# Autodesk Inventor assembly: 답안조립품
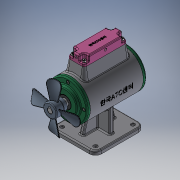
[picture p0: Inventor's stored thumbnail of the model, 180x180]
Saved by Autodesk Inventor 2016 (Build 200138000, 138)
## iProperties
Created: 2021-02
Part Number: 답안조립품
Material: 일반
Document SubType Name: Assembly
Designer: Windows7
Mass: 2275.07 g
Surface Area: 2702.32 cm^2
Volume: 961.297 cm^3
Density: 2.36666 g/cm^3
Author: Windows7
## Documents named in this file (19)
- C:\Users\Windows7\Desktop\610204V1013\답안조립품.iam
- C:\Users\Windows7\Desktop\610204V1013\본체.ipt
- C:\Users\Windows7\Desktop\610204V1013\가변스프링1.ipt
- C:\Users\Windows7\Desktop\610204V1013\가변스프링2.ipt
- C:\Users\Windows7\Desktop\610204V1013\가변스프링3.ipt
- C:\Users\Windows7\Desktop\610204V1013\뒤커버.ipt
- C:\Users\Windows7\Desktop\610204V1013\멈춤나사 M4 x 8.ipt
- C:\Users\Windows7\Desktop\610204V1013\베어링 6203.ipt
- C:\Users\Windows7\Desktop\610204V1013\볼트 M4 x 12.ipt
- C:\Users\Windows7\Desktop\610204V1013\볼트 M4 x 16.ipt
- C:\Users\Windows7\Desktop\610204V1013\부시.ipt
- C:\Users\Windows7\Desktop\610204V1013\슬라이드.ipt
- C:\Users\Windows7\Desktop\610204V1013\앞커버.ipt
- C:\Users\Windows7\Desktop\610204V1013\오일실 17 30 8.ipt
- C:\Users\Windows7\Desktop\610204V1013\축.ipt
- C:\Users\Windows7\Desktop\610204V1013\키 5 x 5 x 26.ipt
- C:\Users\Windows7\Desktop\610204V1013\팬날개.ipt
- 팬날개.ipt
- C:\Users\Windows7\Desktop\610204V1013\헤더커버.ipt
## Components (4 placed, 4 different names)
1. 가변스프링1:1
2. 가변스프링2:1
3. 가변스프링3:1
4. 헤더커버:1 — 각도:2, 각도:3
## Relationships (2: Angle 2)
- 각도:2 [Angle]: 헤더커버:1
- 각도:3 [Angle]: 헤더커버:1
